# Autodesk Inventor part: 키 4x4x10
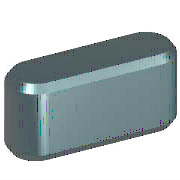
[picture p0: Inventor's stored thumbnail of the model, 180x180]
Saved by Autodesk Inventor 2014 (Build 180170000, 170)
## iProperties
IsCustomPart: 1
Created: 2012-02
Part Number: 키 4x4x10
Material: 강철, 연강
Description: 키 및 해당 키홈
Document SubType Name: Modeling
Standard: KS B 1311
Designer: test
Standards Organization: KS
Language: ko-KR
Size Designation: 4 x 4 x 10
Categories: <MemberInstance><Categories><Category DisplayName="샤프트 부품" InternalName="7f7aeb1f-a693-4053-b835-cee3144e0d98" Mnemonic="SHFT"><Category DisplayName="키" Interna
Density: 1 g/cm^3
Appearance: Yellow
Author: test
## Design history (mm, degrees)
sketch "스케치1"
  geometry: L1 (2, 2)-(8, 2); L2 (8, -2)-(2, -2); L3 (0, 9.4)-(0, -7.4) reference; L4 (-5, 0)-(30, 0) reference; L5 (10, 0)-(10, 7); A1 r 2 centre (2, 0) between (2, 2) and (2, -2); A2 r 2 centre (8, 0) between (8, -2) and (8, 2)
  constraints: 6 end point, 5 point on circle, 4 tangent, 3 point on line, 2 centre point, 1 horizontal, 1 parallel, 1 perpendicular
  dimensions: "d0" = 2 radius of A1 (= 0.5 x PB); "d13" = 2 radius of A2 (= 0.5 x PB); "d14" = 10 distance between parallel lines of L5 L3 (= NLG)
extrude "본체1" new body sketch "스케치1" taper "d3" = 0 deg; stored distance "d4" = 10
workplane "Work Plane3"
body "Solid1"
workplane "Work Plane1"
workplane "Work Plane2"
chamfer "모따기1" distance "d8" = 0.25 (= PHH); stored, may be unused: second distance "d9" = 0.25 (= PHH), angle "d15" = 45 deg
other parameters: "d1" = -2.5 (= -PNT), "d2" = 1.5 (= PH - PNT), "NLG" = 10 [user parameter; used in 3 equation terms], "PB" = 4 [user parameter; used in 2 equation terms], "PNT" = 2.5 [user parameter; used in 2 equation terms], "PH" = 4 [user parameter; used in 1 equation term], "PHH" = 0.25 [user parameter; used in 2 equation terms], "d10" = 0, "d16" = 0, "d17" = 0, "d18" = 0, "WDMAX" = 12 [user parameter], "RR" = 0.08 [user parameter], "PUEB" = 1.8 [user parameter]
